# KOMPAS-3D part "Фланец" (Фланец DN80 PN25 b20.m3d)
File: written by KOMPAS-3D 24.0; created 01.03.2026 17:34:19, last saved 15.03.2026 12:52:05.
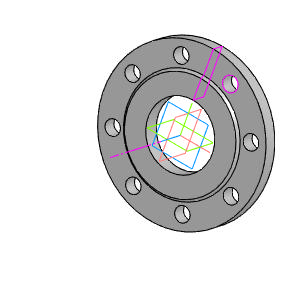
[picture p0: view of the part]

Document properties: Автор: R2D2; Полное имя файла: E:\Работа\Зайцев\GVWR2434M-2W-F-ОСТ Задвижка клиновая с выдвижным штоком DN.ru Ду50-300 Ру25\исходные материалы\DN80\Фланец DN80 PN25 b20.m3d

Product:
- Part/product: Фланец
    Масса: 3.249427
    additional columns: Типовые

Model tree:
1. Эскиз:2
2. Элемент вращения:1
     Угол 1 = 360
3. Эскиз:3  (with: Грань.Элемент вращения:1)
4. Элемент выдавливания:2
     Расстояние 2 = 17
5. Массив по концентрической сетке:1  (with: Элемент выдавливания:2, Эскиз:3, Грань.Элемент вращения:1)  (8 pattern instances)
     Шаг 2 = 360
6. Эскиз:4  (with: Грань.Элемент вращения:1)
7. Элемент выдавливания:3
     Расстояние 2 = 2.5

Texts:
  Линейный размер с обрывом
